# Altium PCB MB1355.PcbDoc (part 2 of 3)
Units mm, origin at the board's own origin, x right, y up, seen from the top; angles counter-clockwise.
Board outline 70.13 x 64.58 mm, 4 copper layers (L1, L2, L3, L4), stack 1.565 mm thick; 206 components, 160 nets, 707 pads, 1364 vias.
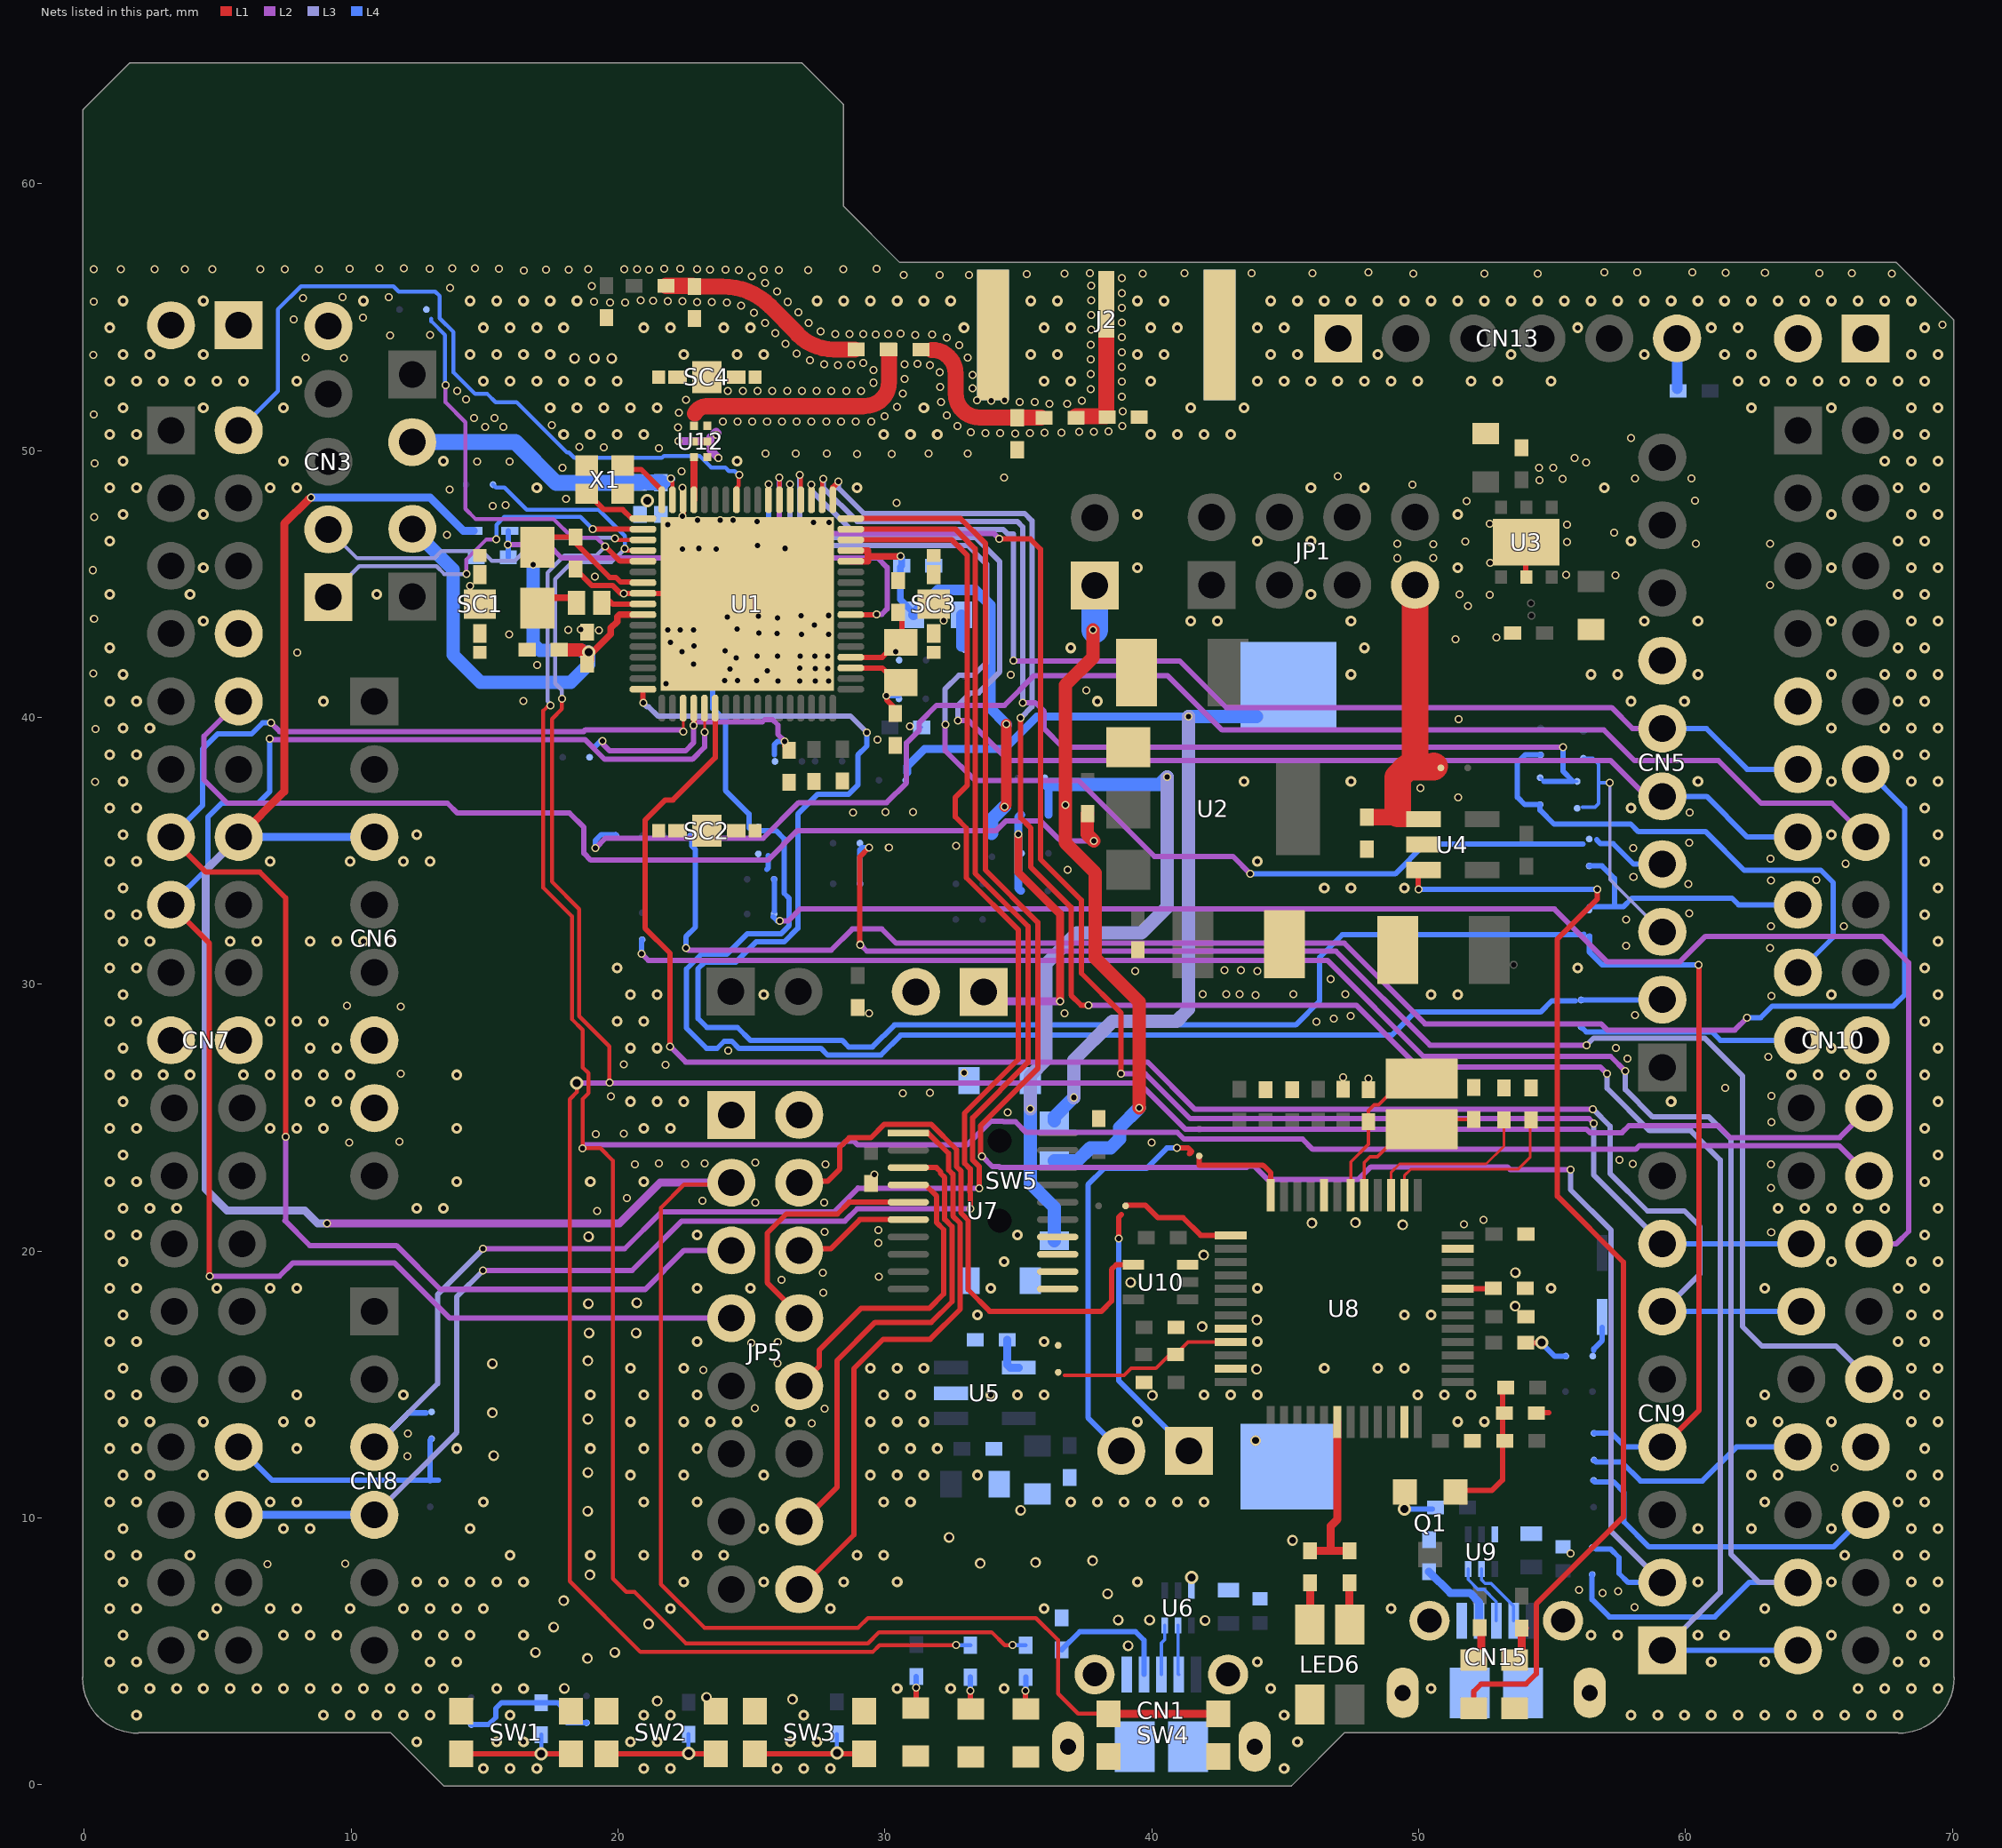
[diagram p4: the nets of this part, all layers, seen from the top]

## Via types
v1: diameter 0.3, hole 0.2, L1 to L4, tented both sides, 662 vias
v2: diameter 0.403, hole 0.2, L1 to L4, tented both sides, 628 vias
v3: diameter 0.4, hole 0.25, L1 to L4, tented both sides, 50 vias
v4: diameter 0.5, hole 0.3, L1 to L4, tented both sides, 24 vias

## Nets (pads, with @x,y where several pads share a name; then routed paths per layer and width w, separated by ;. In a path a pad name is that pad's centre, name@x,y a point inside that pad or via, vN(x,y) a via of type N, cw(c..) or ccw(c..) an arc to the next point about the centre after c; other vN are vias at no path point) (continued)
GND: C1.1 C2.2 C3.1 C6.2 C7.2 C8.2 C9.2 C10.2 C11.2 C12.2 C13.2 C14.2 C15.2 C16.2 C17.2 C18.2 C19.2 C20.2 C21.2 C22.2 C23.2 C24.2 C25.2 C26.2 C27.2 C28.2 C29.2 C31.2 C32.2 C33.1 C34.1 C36.2 C37.1 C39.1 C40.1 C41.2 C42.1 C43.2 C44.1 C45.1 C46.1 C47.2 C48.2 C49.2 C50.2 CN1.5 CN1.6 CN3.5 CN4.2 CN5.7 CN6.6 CN6.7 CN7.8 CN7.19 CN7.20 CN10.9 CN10.20 CN10.32 CN11.1 CN11.2 CN12.1 CN12.2 CN13.1 CN15.5 CN15.6 J2.2 JP5.1 JP5.2 LED1.K LED2.K LED3.K LED5.K LED6.1 R1.1 R6.2 R15.2 R18.2 R19.1 R20.1 R22.2 R23.1 R28.2 SB40.2 SC1.1 SC2.1 SC3.1 SC4.1 SK_BT1.2 SW1.1 SW2.1 SW3.1 SW4.2 SW5.0 U1.32 U1.42 U1.69 U2.1 U3.2 U3.7 U4.2 U5.2 U6.3 U7.11 U7.12 U7.13 U7.14 U8.8 U8.20 U8.23 U8.35 U8.47 U9.3 U10.3 U11.2 U12.A2 U12.B1 U12.B2 U12.B3 U13.2 X1.2 X1.4 | length 16
  L1 w0.2: C29.2@18.408,45.56 19.016,44.952 19.795,44.952 20.095,44.652 v1(20.217,44.652) U1.42@20.941,44.652 U1.69@24.444,44.652 ; U1.32@22.444,48.155 22.444,46.652 U1.69@24.444,44.652 ; U1.69@24.844,44.252 U1.69@24.444,44.652 ; U10.3@41.346,19.486 U10.3@41.543,19.486 ; U3.2@54.006,45.249 U3.7@54.006,46.549 ; R20.1@54.415,13.933 54.432,13.95 54.877,13.95
  L2 w0.3: v1(22.265,50.348) 23.464,50.348 ; v1(23.704,50.581) 23.704,50.623 23.733,50.653 23.674,50.712 23.464,50.502 23.464,50.348 ; v1(23.771,49.717) 23.464,50.024 23.464,50.348
  L4 w0.1: R6.2@31.304,39.705 R6.2@31.38,39.629
  other v1: 58.089,6.659 56.89,7.185 57.479,7.248 56.006,7.312 6.874,8.268 9.773,8.28 55.692,8.664 65.578,11.882 12.106,12.308 12.128,13.159 27.267,13.543 25.131,14.115 27.738,14.101 23.191,15.548 25.975,15.801 24.989,16.555 25.986,16.588 27.699,18.442 26.12,18.92 29.772,19.049 27.683,19.187 29.764,20.312 63.209,20.704 27.746,20.728 29.756,20.782 51.697,21.007 52.429,21.175 19.224,21.5 25.151,21.82 27.73,21.827 23.17,21.88 20.338,21.985 63.198,22.366 29.607,22.864 20.627,23.256 27.767,23.255 63.198,23.251 21.531,23.283 22.514,23.27 23.249,23.283 58.02,23.278 25.142,23.313 57.529,23.417 9.928,24.068 39.992,24.069 11.816,24.106 19.176,24.379 20.219,24.406 63.219,24.838 34.599,25.195 19.734,25.806 63.213,25.81 30.669,25.913 31.694,25.926 61.481,26.123 48.119,26.473 47.162,26.517 11.864,26.655 32.965,26.688 21.787,26.99 20.211,27.005 57.829,27.221 63.099,27.287 24.124,27.513 57.383,27.621 46.167,28.602 46.821,28.721 47.455,28.806 58.1,28.839 29.408,28.92 36.729,28.91 11.853,29.17 9.839,29.191 63.219,29.561 43.897,29.598 41.914,29.622 42.787,29.635 43.298,29.622 45.306,29.635 47.251,29.622 46.703,30.196 39.377,30.489 43.959,30.495 42.725,30.52 43.336,30.533 63.162,31.354 57.771,31.446 65.925,32.172 63.205,32.179 57.771,32.43 60.145,32.663 60.106,33.751 63.205,33.886 64.906,33.903 58.048,34.017 36.849,34.283 65.999,34.515 63.19,34.711 58.035,35.105 30.148,35.125 32.675,35.196 60.145,35.304 28.808,36.439 60.159,36.432 30.015,36.451 31.047,36.457 51.486,36.998 50.072,37.361 0.404,37.581 29.719,39.171 0.422,39.565 30.941,39.672 51.491,39.926 16.455,40.614 37.541,41.021 21.805,41.262 25.989,41.37 26.809,41.363 27.396,41.369 27.884,41.368 23.996,41.375 24.487,41.378 25.194,41.375 34.716,41.6 0.347,41.643 25.601,41.752 24.202,41.814 27.851,41.825 26.813,41.841 27.389,41.837 16.966,41.971 22.825,42.002 24.434,42.224 25.208,42.295 25.974,42.29 26.822,42.297 27.38,42.297 27.866,42.294 7.988,42.427 22.403,42.465 24.017,42.505 22.847,42.684 21.972,42.82 51.378,42.924 52.916,42.989 15.928,43.112 26.871,43.112 27.884,43.112 25.271,43.16 25.966,43.151 19.287,43.27 21.859,43.276 18.144,43.285 18.601,43.291 22.336,43.282 22.832,43.285 24.461,43.32 27.352,43.46 32.199,43.624 0.366,43.702 25.984,43.721 24.095,43.765 25.253,43.801 26.866,43.807 27.884,43.821 51.843,44.182 52.658,44.589 51.534,44.616 14.455,44.924 63.174,44.969 19.127,45.27 57.366,45.333 55.525,45.35 0.329,45.519 52.676,45.793 49.205,45.968 50.548,45.982 22.413,46.302 23.677,46.302 23.023,46.334 26.261,46.334 25.223,46.447 50.552,46.492 49.205,46.502 60.394,46.51 63.161,46.514 55.552,46.572 51.755,46.598 13.594,46.838 57.331,46.926 21.859,47.223 55.561,47.218 52.667,47.253 27.325,47.312 27.903,47.312 25.211,47.337 22.976,47.389 24.312,47.387 23.828,47.396 0.366,47.503 22.419,47.539 15.305,47.917 15.791,47.96 30.433,48.039 51.799,48.112 60.359,48.116 18.049,48.184 13.685,48.547 22.422,48.601 49.759,48.728 54.525,48.882 55.393,48.944 58.11,48.961 60.216,48.952 34.468,48.992 46.973,49.04 22.387,49.224 17.92,49.351 54.516,49.36 55.047,49.36 0.393,49.523 56.278,49.563 14.725,49.596 15.936,49.582 55.835,49.723 28.953,49.869 30.261,49.869 25.529,49.882 26.662,49.894 27.833,49.894 31.631,49.894 33.101,49.881 21.54,50.083 18.551,50.133 19.463,50.128 57.959,50.466 34.876,50.636 33.768,50.654 34.322,50.654 35.429,50.654 33.215,50.692 35.983,50.677 36.611,50.677 37.276,50.697 37.829,50.708 38.383,50.724 15.015,50.882 15.71,50.889 22.247,50.875 38.901,50.92 32.711,50.923 17.525,50.951 23.924,51.081 24.478,51.081 25.032,51.081 25.586,51.081 26.14,51.081 26.694,51.081 27.248,51.081 27.802,51.081 28.356,51.081 28.91,51.081 29.482,51.094 14.603,51.217 15.376,51.217 29.99,51.281 32.323,51.317 0.351,51.352 22.28,51.417 38.918,51.474 30.455,51.638 36.159,51.755 36.835,51.758 32.107,51.828 35.054,51.822 35.608,51.816 33.977,51.87 34.485,51.882 37.378,51.87 22.543,51.905 33.448,51.888 14.314,51.912 38.877,52.026 30.673,52.131 13.973,52.242 24.12,52.243 24.674,52.243 25.228,52.243 25.782,52.243 26.336,52.243 26.89,52.243 27.444,52.243 27.998,52.243 28.552,52.243 29.106,52.243 37.715,52.31 33.28,52.331 32.073,52.38 29.571,52.544 38.877,52.58 30.739,52.681 33.28,52.838 37.715,52.864 32.06,52.934 29.57,53.012 38.877,53.134 31.688,53.198 28.242,53.209 28.741,53.215 27.725,53.24 30.739,53.235 31.214,53.247 29.195,53.277 27.188,53.378 37.715,53.418 8.295,53.481 9.731,53.469 33.097,53.489 0.34,53.581 26.697,53.634 38.877,53.688 32.782,53.944 26.277,53.995 37.715,53.972 32.313,54.24 38.877,54.242 11.468,54.311 12.962,54.333 29.654,54.35 31.131,54.338 28.142,54.372 28.681,54.374 29.183,54.371 30.126,54.367 31.772,54.357 25.895,54.396 30.59,54.376 27.597,54.47 37.723,54.526 69.63,54.721 25.504,54.789 27.143,54.788 38.873,54.796 7.855,54.909 10.443,54.978 37.723,55.08 25.097,55.164 26.753,55.181 38.873,55.35 24.615,55.438 19.709,55.555 20.264,55.555 22.966,55.557 24.074,55.557 0.361,55.589 19.107,55.579 21.859,55.592 22.413,55.592 23.52,55.57 26.362,55.574 21.318,55.618 20.843,55.626 37.723,55.634 8.19,55.716 9.682,55.746 11.417,55.754 38.873,55.904 25.962,55.957 13.704,56.094 19.012,56.157 37.723,56.188 25.514,56.283 38.873,56.458 25.016,56.526 30.708,56.586 32.046,56.586 33.153,56.586 35.321,56.609 36.728,56.632 39.657,56.632 49.805,56.632 52.458,56.632 54.464,56.632 67.729,56.636 37.686,56.641 41.225,56.655 43.739,56.655 46.023,56.655 65.009,56.649 66.224,56.649 48.122,56.678 56.956,56.676 58.196,56.675 60.256,56.675 61.51,56.662 62.976,56.662 16.466,56.752 17.301,56.773 18.146,56.783 21.168,56.783 23.448,56.786 24.032,56.786 24.531,56.771 25.468,56.786 26.026,56.77 27.134,56.77 0.361,56.805 1.375,56.805 2.644,56.794 3.774,56.805 4.81,56.805 6.607,56.805 7.515,56.805 8.805,56.805 18.886,56.794 20.231,56.791 20.712,56.797 21.729,56.807 22.331,56.807 22.957,56.795 28.448,56.793 9.946,56.815 11.055,56.836 11.975,56.826 12.936,56.815 13.792,56.826 14.648,56.826 15.547,56.815 29.694,56.816
  other v2: 14.962,0.607 15.962,0.607 16.962,0.607 20.962,0.607 21.962,0.607 25.962,0.607 26.962,0.607 27.962,0.607 44.962,0.607 12.462,1.607 15.462,1.607 16.462,1.607 20.462,1.607 21.462,1.607 26.462,1.607 27.462,1.607 45.462,1.607 1.962,2.607 8.962,2.607 9.962,2.607 10.962,2.607 11.962,2.607 12.962,2.607 15.962,2.607 20.962,2.607 21.962,2.607 26.962,2.607 44.962,2.607 57.962,2.607 58.962,2.607 59.962,2.607 60.962,2.607 61.962,2.607 62.962,2.607 63.962,2.607 64.962,2.607 65.962,2.607 66.962,2.607 67.962,2.607 1.462,3.607 2.462,3.607 3.462,3.607 4.462,3.607 5.462,3.607 6.462,3.607 7.462,3.607 8.462,3.607 9.462,3.607 10.462,3.607 11.462,3.607 12.462,3.607 13.462,3.607 15.462,3.607 16.462,3.607 30.462,3.607 32.462,3.607 34.462,3.607 44.462,3.607 50.462,3.607 66.462,3.607 67.462,3.607 68.462,3.607 69.462,3.607 0.962,4.607 1.962,4.607 12.962,4.607 13.962,4.607 43.962,4.607 60.962,4.607 62.962,4.607 67.962,4.607 68.962,4.607 1.462,5.607 4.462,5.607 7.462,5.607 8.462,5.607 9.462,5.607 12.462,5.607 13.462,5.607 14.462,5.607 16.462,5.607 56.462,5.607 57.462,5.607 60.462,5.607 61.462,5.607 65.462,5.607 68.462,5.607 69.462,5.607 0.962,6.607 1.962,6.607 4.962,6.607 6.962,6.607 7.962,6.607 9.962,6.607 11.962,6.607 12.962,6.607 13.962,6.607 14.962,6.607 21.962,6.607 27.962,6.607 35.962,6.607 48.962,6.607 62.962,6.607 67.962,6.607 68.962,6.607 1.462,7.607 12.462,7.607 13.462,7.607 14.462,7.607 15.462,7.607 16.462,7.607 22.462,7.607 25.462,7.607 28.462,7.607 30.462,7.607 39.462,7.607 60.462,7.607 65.462,7.607 68.462,7.607 69.462,7.607 0.962,8.607 1.962,8.607 3.962,8.607 15.962,8.607 18.962,8.607 20.962,8.607 22.962,8.607 23.962,8.607 28.962,8.607 29.962,8.607 65.962,8.607 67.962,8.607 68.962,8.607 1.462,9.607 7.462,9.607 8.462,9.607 14.462,9.607 25.462,9.607 60.462,9.607 62.462,9.607 65.462,9.607 68.462,9.607 69.462,9.607 0.962,10.607 1.962,10.607 6.962,10.607 7.962,10.607 14.962,10.607 20.962,10.607 22.962,10.607 29.962,10.607 30.962,10.607 36.962,10.607 37.962,10.607 38.962,10.607 39.962,10.607 40.962,10.607 41.962,10.607 62.962,10.607 67.962,10.607 68.962,10.607 1.462,11.607 2.462,11.607 4.462,11.607 20.462,11.607 22.462,11.607 25.462,11.607 29.462,11.607 30.462,11.607 31.462,11.607 33.462,11.607 62.462,11.607 63.462,11.607 68.462,11.607 69.462,11.607 0.962,12.607 1.962,12.607 7.962,12.607 13.962,12.607 18.962,12.607 20.962,12.607 22.962,12.607 29.962,12.607 30.962,12.607 31.962,12.607 68.962,12.607 1.462,13.607 2.462,13.607 4.462,13.607 7.462,13.607 8.462,13.607 20.462,13.607 22.462,13.607 23.462,13.607 24.462,13.607 26.462,13.607 29.462,13.607 30.462,13.607 31.462,13.607 39.462,13.607 51.462,13.607 52.462,13.607 62.462,13.607 63.462,13.607 65.462,13.607 68.462,13.607 69.462,13.607 0.962,14.607 1.962,14.607 7.962,14.607 11.962,14.607 18.962,14.607 20.962,14.607 22.962,14.607 29.962,14.607 30.962,14.607 33.962,14.607 34.962,14.607 35.962,14.607 41.962,14.607 42.962,14.607 43.962,14.607 49.962,14.607 50.962,14.607 51.962,14.607 62.962,14.607 67.962,14.607 68.962,14.607 1.462,15.607 20.462,15.607 22.462,15.607 29.462,15.607 30.462,15.607 31.462,15.607 46.462,15.607 48.462,15.607 49.462,15.607 68.462,15.607 69.462,15.607 0.962,16.607 1.962,16.607 22.962,16.607 35.962,16.607 43.962,16.607 67.962,16.607 68.962,16.607 1.462,17.607 33.462,17.607 49.462,17.607 50.462,17.607 68.462,17.607 69.462,17.607 0.962,18.607 1.962,18.607 4.962,18.607 6.962,18.607 7.962,18.607 22.962,18.607 24.962,18.607 33.962,18.607 43.962,18.607 54.962,18.607 62.962,18.607 67.962,18.607 68.962,18.607 1.462,19.607 34.462,19.607 65.462,19.607 68.462,19.607 69.462,19.607 0.962,20.607 1.962,20.607 22.962,20.607 34.962,20.607 68.962,20.607 1.462,21.607 2.462,21.607 3.462,21.607 12.462,21.607 13.462,21.607 63.462,21.607 64.462,21.607 65.462,21.607 66.462,21.607 67.462,21.607 69.462,21.607 0.962,22.607 1.962,22.607 13.962,22.607 18.962,22.607 20.962,22.607 68.962,22.607 1.462,23.607 69.462,23.607 0.962,24.607 1.962,24.607 6.962,24.607 7.962,24.607 8.962,24.607 13.962,24.607 20.962,24.607 21.962,24.607 68.962,24.607 1.462,25.607 8.462,25.607 9.462,25.607 20.462,25.607 21.462,25.607 22.462,25.607 59.462,25.607 69.462,25.607 0.962,26.607 1.962,26.607 2.962,26.607 3.962,26.607 5.962,26.607 6.962,26.607 7.962,26.607 8.962,26.607 9.962,26.607 13.962,26.607 63.962,26.607 64.962,26.607 65.962,26.607 66.962,26.607 68.962,26.607 1.462,27.607 8.462,27.607 9.462,27.607 20.462,27.607 21.462,27.607 65.462,27.607 69.462,27.607 0.962,28.607 1.962,28.607 6.962,28.607 7.962,28.607 8.962,28.607 19.962,28.607 20.962,28.607 68.962,28.607 1.462,29.607 20.462,29.607 21.462,29.607 25.462,29.607 50.462,29.607 51.462,29.607 65.462,29.607 69.462,29.607 0.962,30.607 1.962,30.607 19.962,30.607 55.962,30.607 68.962,30.607 1.462,31.607 2.462,31.607 5.462,31.607 6.462,31.607 8.462,31.607 9.462,31.607 10.462,31.607 11.462,31.607 69.462,31.607 0.962,32.607 1.962,32.607 68.962,32.607 1.462,33.607 46.462,33.607 47.462,33.607 49.462,33.607 69.462,33.607 0.962,34.607 1.962,34.607 6.962,34.607 9.962,34.607 11.962,34.607 12.962,34.607 43.962,34.607 68.962,34.607 1.462,35.607 12.462,35.607 65.462,35.607 69.462,35.607 0.962,36.607 1.962,36.607 57.962,36.607 68.962,36.607 1.462,37.607 43.462,37.607 47.462,37.607 60.462,37.607 65.462,37.607 68.462,37.607 69.462,37.607 0.962,38.607 1.962,38.607 67.962,38.607 68.962,38.607 1.462,39.607 2.462,39.607 65.462,39.607 67.462,39.607 68.462,39.607 69.462,39.607 0.962,40.607 1.962,40.607 8.962,40.607 37.962,40.607 57.962,40.607 59.962,40.607 67.962,40.607 68.962,40.607 1.462,41.607 47.462,41.607 56.462,41.607 57.462,41.607 60.462,41.607 65.462,41.607 67.462,41.607 68.462,41.607 69.462,41.607 0.962,42.607 36.962,42.607 47.962,42.607 67.962,42.607 68.962,42.607 4.462,43.607 41.462,43.607 42.462,43.607 47.462,43.607 58.462,43.607 60.462,43.607 65.462,43.607 68.462,43.607 69.462,43.607 0.962,44.607 3.962,44.607 10.962,44.607 45.962,44.607 67.962,44.607 68.962,44.607 4.462,45.607 39.462,45.607 51.462,45.607 65.462,45.607 68.462,45.607 69.462,45.607 0.962,46.607 43.962,46.607 45.962,46.607 57.962,46.607 67.962,46.607 68.962,46.607 1.462,47.607 4.462,47.607 39.462,47.607 51.462,47.607 65.462,47.607 68.462,47.607 69.462,47.607 0.962,48.607 1.962,48.607 6.962,48.607 7.962,48.607 16.962,48.607 28.962,48.607 45.962,48.607 47.962,48.607 56.962,48.607 67.962,48.607 68.962,48.607 1.462,49.607 7.462,49.607 13.462,49.607 24.462,49.607 67.462,49.607 68.462,49.607 69.462,49.607 0.962,50.607 1.962,50.607 17.962,50.607 18.962,50.607 19.962,50.607 20.962,50.607 29.962,50.607 30.962,50.607 31.962,50.607 39.962,50.607 40.962,50.607 41.962,50.607 42.962,50.607 67.962,50.607 68.962,50.607 1.462,51.607 4.462,51.607 7.462,51.607 17.462,51.607 18.462,51.607 19.462,51.607 20.462,51.607 21.462,51.607 31.462,51.607 41.462,51.607 43.462,51.607 62.462,51.607 65.462,51.607 68.462,51.607 69.462,51.607 0.962,52.607 1.962,52.607 2.962,52.607 3.962,52.607 4.962,52.607 5.962,52.607 7.962,52.607 14.962,52.607 15.962,52.607 16.962,52.607 17.962,52.607 18.962,52.607 19.962,52.607 35.962,52.607 36.962,52.607 39.962,52.607 43.962,52.607 44.962,52.607 45.962,52.607 46.962,52.607 47.962,52.607 48.962,52.607 49.962,52.607 51.962,52.607 52.962,52.607 54.962,52.607 61.962,52.607 62.962,52.607 63.962,52.607 64.962,52.607 65.962,52.607 66.962,52.607 67.962,52.607 68.962,52.607 1.462,53.607 2.462,53.607 4.462,53.607 14.462,53.607 15.462,53.607 16.462,53.607 17.462,53.607 22.462,53.607 24.462,53.607 25.462,53.607 35.462,53.607 36.462,53.607 39.462,53.607 40.462,53.607 44.462,53.607 45.462,53.607 48.462,53.607 53.462,53.607 58.462,53.607 61.462,53.607 62.462,53.607 68.462,53.607 69.462,53.607 0.962,54.607 14.962,54.607 15.962,54.607 16.962,54.607 17.962,54.607 20.962,54.607 21.962,54.607 23.962,54.607 24.962,54.607 32.962,54.607 35.962,54.607 36.962,54.607 39.962,54.607 40.962,54.607 43.962,54.607 44.962,54.607 55.962,54.607 60.962,54.607 61.962,54.607 68.962,54.607 1.462,55.607 4.462,55.607 10.462,55.607 14.462,55.607 15.462,55.607 16.462,55.607 17.462,55.607 18.462,55.607 27.462,55.607 28.462,55.607 29.462,55.607 30.462,55.607 31.462,55.607 32.462,55.607 35.462,55.607 36.462,55.607 39.462,55.607 40.462,55.607 44.462,55.607 45.462,55.607 46.462,55.607 47.462,55.607 48.462,55.607 49.462,55.607 50.462,55.607 51.462,55.607 52.462,55.607 53.462,55.607 54.462,55.607 55.462,55.607 56.462,55.607 57.462,55.607 58.462,55.607 59.462,55.607 60.462,55.607 61.462,55.607 62.462,55.607 63.462,55.607 64.462,55.607 65.462,55.607 66.462,55.607 67.462,55.607 68.462,55.607
  other v3: 21.468,3.14 26.541,3.202 23.321,3.279 17.987,3.611 18.859,4.734 16.908,4.964 19.881,4.959 39.114,5.213 17.589,5.907 21.142,6.031 41.994,6.163 38.741,6.178 39.919,6.178 17.966,6.903 38.346,7.158 18.951,7.867 33.575,8.297 35.647,8.336 37.784,8.4 45.278,9.161 32.403,9.275 18.866,10.252 35.086,10.291 18.874,11.701 15.342,12.333 43.89,12.9 18.874,13.706 15.297,13.944 40.021,14.59 43.928,15.579 15.297,15.779 18.874,15.89 18.917,16.933 20.677,16.933 41.889,17.175 43.938,17.422 53.618,17.942 18.892,18.029 20.703,18.063 39.205,18.833 53.625,19.193 41.945,19.849 18.9,20.548 49.4,20.983 46.002,21.051 47.634,21.07 18.37,53.457 19.116,53.457 19.762,53.457
  other v4: 41.485,7.776 21.099,48.131
LED_STLK: R25.2 R27.2 U8.30 | length 6.4
  L1 w0.3: R25.2@45.93,8.773 46.71,8.773 ; U8.30@46.96,13.596 46.96,9.952 46.71,9.702 46.71,8.773 ; R27.2@47.41,8.773 46.71,8.773
NetC3_2: C3.2 D1.A U1.8 | length 18.6
  L1 w0.2: U1.8@28.723,43.851 U1.8@28.722,43.852 29.677,43.852 v1(29.695,43.87)
  L2 w0.2: v1(15.88,46.479) 17.382,46.479 17.886,45.975 20.106,45.975 20.112,45.969 20.402,45.969 20.408,45.975 22.246,45.975 22.268,45.952 22.558,45.952 22.58,45.975 23.509,45.975 23.532,45.952 23.822,45.952 23.844,45.975 24.275,45.975 29.732,45.975 30.087,45.62 30.087,44.069 29.888,43.87 v1(29.695,43.87)
  L4 w0.2: C3.2@15.881,45.998 D1.A@15.881,46.998
NetC6_1: C6.1 SB45.1 U1.3 X2.1 | length 3.1
  L1 w0.2: U1.3@28.722,41.852 29.899,41.852 X2.1@30.444,41.307 ; v1(30.058,40.815) 30.07,40.803 30.07,40.654 C6.1@30.393,40.331
  L4 w0.2: v1(30.058,40.815) 30.529,40.815 30.545,40.831
NetC7_1: C7.1 SB46.1 U1.4 X2.2 | length 3
  L1 w0.2: U1.4@28.722,42.252 29.899,42.252 30.454,42.807 X2.2@30.591,42.807 30.643,42.859 C7.1@30.643,43.695
  other v1: 30.403,42.461
NetC12_1: C12.1 JP1.7 SB25.1 U4.1 | length 11.7
  L1 w0.6: C12.1@48.268,36.263 49.131,36.263 49.212,36.182 U4.1@50.175,36.182
  L1 w1: 49.215,36.394 49.215,37.76 49.595,38.14 49.865,38.14 ; JP1.7@49.865,44.965 49.865,38.14 ; 50.569,38.192 50.595,38.166 50.569,38.14 49.865,38.14
NetC23_1: C23.1 C24.1 JP6.2 SB31.2 U1.44 | length 15.4
  L1 w0.25: C24.1@18.999,42.147 18.999,42.386 19.732,43.119 19.732,43.347 19.975,43.59 19.975,43.773 20.054,43.852 U1.44@20.941,43.852
  L1 w0.5: C23.1@18.076,42.528 18.618,42.528
  L4 w0.5: JP6.2@12.296,47.063 13.824,45.535 13.824,42.342 14.844,41.322 18.232,41.322 18.895,41.984 v4(18.895,42.446) 18.697,42.446 18.637,42.506
NetC26_1: C26.1 U5.4 | length 1.4
  L4 w0.3: C26.1@34.589,16.674 34.589,15.743 34.695,15.636 U5.4@35.02,15.636
NetC29_1: C29.1 L1.1 SB31.1 U1.41 | length 8.7
  L1 w0.2: L1.1@16.98,46.377 17.36,46.758 C29.1@18.408,46.758 18.408,46.529 19.685,45.252 19.919,45.252 20.101,45.07 20.941,45.07 U1.41@20.941,45.052
  L4 w0.5: v1(16.817,45.726) 16.817,42.763 17.074,42.506 SB31.1@17.502,42.506
NetC31_1: C31.1 SB33.1 SB34.1 U1.55 | length 10.7
  L1 w0.2: v1(22.836,39.702) 22.835,39.702 22.844,39.711 U1.55@22.844,40.349 ; v1(26.249,39.108) 26.249,38.922 C31.1@26.409,38.762
  L2 w0.2: v1(19.411,39.111) 19.411,39.029 19.692,38.748 22.531,38.748 22.836,39.053 v1(22.836,39.702) 22.836,39.718 22.951,39.833 25.412,39.833 25.5,39.921 25.79,39.921 25.995,39.716 25.995,39.362 v1(26.249,39.108)
  L4 w0.2: 19.122,38.894 19.339,39.111 v1(19.411,39.111) ; 25.863,38.605 25.863,38.991 25.98,39.108 v1(26.249,39.108)
NetC32_1: C32.1 L2.2 SB49.1 U1.13 U1.14 | length 17.8
  L1 w0.25: U1.13@28.722,45.852 29.365,45.852 29.365,46.252 U1.14@28.722,46.252 ; 29.491,46.042 30.588,46.042 v1(30.592,46.046)
  L1 w0.4: v1(34.485,36.659) 34.551,36.725 v1(34.551,39.746)
  L4 w0.25: v1(30.592,46.046) 30.631,46.007 C32.1@30.631,45.689 30.576,45.634 30.576,44.416 31.063,43.929 L2.2@31.063,43.852
  L4 w0.4: L2.2@31.063,43.852 31.985,44.774 33.387,44.774 33.943,44.218 33.943,40.354 v1(34.551,39.746) v1@34.559,39.738
  L4 w0.5: 33.994,35.649 33.994,36.168 v1(34.485,36.659)
NetC33_2: C33.2 C34.2 JP4.2 U1.33 | length 10.7
  L1 w0.15: U1.33@22.044,48.155 v1@22.044,48.884
  L4 w0.3: C34.2@21.752,48.698 v1@21.991,48.937
  L4 w0.6: JP4.2@12.289,50.316 16.154,50.316 17.679,48.791 20.371,48.791 20.384,48.804 C33.2@20.828,48.804 ; 21.155,48.799 C34.2@21.611,48.799
  other v1: 21.988,48.952
NetC36_1: C36.1 L3.1 R5.2 | length 7.9
  L1 w0.32: C36.1@22.798,56.173 C36.1@22.82,56.151 ; 26.728,54.383 26.728,54.387
  L1 w0.6: L3.1@21.8,56.173 C36.1@22.798,56.173 ; C36.1@22.82,56.151 23.912,56.151 cw(c23.912,53.611) 25.708,55.407 26.728,54.383 ; 26.728,54.358 ccw(c28.097,55.726) 28.097,53.791 R5.2@28.881,53.791
NetC39_2: C39.2 L4.1 R13.2 | length 5.8
  L1 w0.6: 31.754,53.775 cw(c31.754,52.875) 32.654,52.875 32.654,52.179 ; 32.655,52.135 ccw(c33.555,52.135) 33.555,51.235 L4.1@35.841,51.235
NetC40_2: C40.2 J2.1 L4.2 | length 5.3
  L1 w0.32: C40.2@38.275,51.289 C40.2@38.296,51.31 ; J2.1@38.298,54.253 J2.1@38.298,55.481
  L1 w0.6: L4.2@37.169,51.289 C40.2@38.275,51.289 ; C40.2@38.296,51.31 38.296,54.251 J2.1@38.298,54.253
NetC44_2: C44.2 U8.6 X3.2 | length 5.3
  L1 w0.127: U8.6@47.46,22.096 47.46,23.346 48.12,24.006 C44.2@48.12,24.857 48.12,25.269 48.337,25.486 48.496,25.486 49.138,26.128 X3.2@49.138,26.65
NetC45_2: C45.2 U8.5 X3.1 | length 5.8
  L1 w0.127: U8.5@47.96,22.096 47.96,23.316 48.178,23.534 48.446,23.534 49.362,24.45 X3.1@50.738,24.45 ; X3.1@50.942,24.44 51.435,24.933 C45.2@52.064,24.933
NetCN1_2: CN1.2 U6.5 | length 1.9
  L4 w0.12: U6.5@40.986,5.98 40.978,5.973 40.978,4.167 CN1.2@41.009,4.135
NetCN1_3: CN1.3 U6.6 | length 1.9
  L4 w0.12: CN1.3@40.359,4.135 40.359,5.315 40.486,5.442 U6.6@40.486,5.98
NetCN1_4: CN1.4 R1.2 | length 4.8
  L4 w0.2: R1.2@36.627,5.061 37.299,5.733 39.394,5.733 39.709,5.418 CN1.4@39.709,4.135
NetCN3_1: CN3.1 U1.36 | length 14.2
  L1 w0.2: v1@19.044,47.052 19.058,47.065 20.927,47.065 U1.36@20.941,47.052
  L2 w0.15: v1(14.324,45.376) 14.324,45.925 15.072,46.674 v1(15.433,46.674)
  L3 w0.15: CN3.1@9.146,44.507 10.308,45.669 13.198,45.669 13.491,45.376 v1(14.324,45.376)
  L4 w0.15: v1(15.433,46.674) 15.433,46.644 15.445,46.632 15.445,47.22 15.738,47.514 18.595,47.514 v1(19.044,47.064)
NetCN3_2: CN3.2 U1.37 | length 13
  L1 w0.15: v1(19.886,46.715) 19.886,46.663 19.905,46.644 U1.37@20.933,46.644 ; U1.37@20.915,46.626 U1.37@20.933,46.644 ; U1.37@20.941,46.652 U1.37@20.933,46.644 ; U1.37@20.957,46.644 U1.37@20.933,46.644
  L3 w0.15: CN3.2@9.146,47.047 10.231,45.962 13.116,45.962 13.394,46.24 14.894,46.24 15.271,45.863 16.127,45.863 17.002,46.738 19.863,46.738 v1(19.886,46.715)
NetCN4_1: CN4.1 SB24.1 SB27.1 SB28.1 | length 12.8
  L1 w0.3: v1(35.008,35.615) 35.008,34.184 36.558,32.634 v1(36.558,29.366)
  L2 w0.3: CN4.1@33.71,29.707 34.051,29.366 v1(36.558,29.366)
  L4 w0.3: SB24.1@35.097,33.5 34.997,33.6 34.997,36.261 SB27.1@35.097,36.361
NetCN5_3: CN5.3 SB41.2 SB42.2 | length 9.6
  L3 w0.127: v1(57.165,37.557) 57.165,33.929 CN5.3@59.13,31.964
  L4 w0.127: 56.133,36.633 56.604,36.633 56.746,36.776 56.746,37.556 ; SB42.2@56.17,38.468 56.522,38.468 56.746,38.243 56.746,37.556 ; v1(57.165,37.557) 56.748,37.557 56.746,37.556
NetCN7_10: CN7.10 R33.1 | length 40.7
  L1 w0.5: R33.1@37.593,36.396 37.583,36.386 37.583,35.62 v1(37.828,35.375)
  L2 w0.2: CN7.10@5.79,40.6 4.487,39.297 4.487,37.662 5.363,36.787 13.609,36.787 13.977,36.419 18.188,36.419 18.722,35.885 18.722,34.911 18.98,34.653 25.619,34.653 26.723,35.757 34.172,35.757 34.54,36.125 35.827,36.125 36.504,35.448 36.522,35.448 36.595,35.375 v1(37.828,35.375)
NetCN7_32: CN7.32 SB14.1 SB16.1 | length 9.6
  L4 w0.2: CN7.32@5.79,12.66 7.038,11.412 13.278,11.412 ; SB16.1@12.962,11.426 12.962,12.915 SB14.1@13.016,12.969
NetCN10_12: CN10.12 SB2.2 | length 61.6
  L2 w0.2: v1(22.541,31.362) 22.626,31.277 27.986,31.277 28.778,32.069 29.891,32.069 30.416,31.543 47.213,31.543 50.24,28.516 56.839,28.516 57.068,28.287 61.848,28.287 v1(62.308,28.747)
  L4 w0.2: v1(22.541,31.362) 22.541,31.783 22.902,32.144 22.902,35.052 22.758,35.196 22.758,35.522 SB2.2@22.718,35.562 ; v1(62.308,28.747) 62.814,28.747 63.249,29.182 67.782,29.182 68.21,29.61 68.21,36.6 CN10.12@66.75,38.06
NetCN10_14: CN10.14 SB4.2 | length 55
  L2 w0.2: v1(19.158,35.099) 19.53,35.471 25.436,35.471 26.771,36.806 30.068,36.806 30.813,37.551 30.813,39.049 31.291,39.527 31.291,39.806 31.935,40.45 34.477,40.45 35.595,41.568 35.595,41.573 40.591,41.573 42.635,39.529 56.941,39.529 58.084,38.386 61.231,38.386 62.829,36.788 65.482,36.788 CN10.14@66.75,35.52
  L3 w0.2: v1@19.156,35.099 v1(19.158,35.099)
  L4 w0.2: v1(19.158,35.099) 19.158,35.396 19.366,35.604 SB4.2@19.919,35.604
NetCN10_15: CN10.15 SB1.1 SB3.1 | length 10.2
  L4 w0.2: SB1.1@56.39,34.434 56.869,34.434 57.334,33.969 57.334,32.904 ; SB3.1@56.4,32.904 57.334,32.904 ; CN10.15@64.21,32.98 61.984,32.98 61.74,33.224 57.99,33.224 57.67,32.904 57.334,32.904
NetCN10_17: CN10.17 SB5.1 SB6.1 | length 19.5
  L4 w0.2: SB6.1@54.57,38.594 53.988,38.594 53.702,38.308 53.702,37.012 53.98,36.734 SB5.1@54.55,36.734 54.55,36.524 55.07,36.004 57.945,36.004 58.235,35.714 60.759,35.714 62.199,34.274 65.07,34.274 65.53,33.814 65.53,31.76 CN10.17@64.21,30.44
NetCN10_19: CN10.19 SB8.1 | length 8.3
  L4 w0.2: SB8.1@56.09,28.404 56.28,28.214 60.99,28.214 61.304,27.9 CN10.19@64.21,27.9
NetCN10_26: CN10.26 SB7.2 SB9.2 SB10.2 | length 57.9
  L2 w0.2: v1(26.065,32.377) 26.379,32.377 26.821,32.819 55.09,32.819 57.069,30.84 59.784,30.84 60.745,31.801 67.363,31.801 68.36,30.804 68.36,20.738 67.902,20.28 CN10.26@66.877,20.28
  L4 w0.2: 25.573,34.302 25.626,34.355 25.626,34.821 ; SB7.2@25.811,32.528 25.962,32.377 v1(26.065,32.377) ; SB9.2@25.848,33.937 25.855,33.93 SB7.2@25.855,32.739
NetCN10_30: CN10.30 SB12.2 SB13.2 | length 55.7
  L1 w0.2: v1(29.081,31.485) 29.061,31.485 29.061,34.781 v1(29.404,35.124)
  L2 w0.2: v1(29.081,31.485) 29.323,31.243 46.895,31.243 50.419,27.719 v1(56.291,27.719)
  L3 w0.2: v1(56.291,27.719) 56.557,27.985 57.947,27.985 57.948,27.984 60.717,27.984 62.127,26.574 62.127,17.178 62.861,16.444 65.633,16.444 CN10.30@66.877,15.2
  L4 w0.2: SB12.2@29.052,33.784 29.052,35.035 29.141,35.124 v1(29.404,35.124)
NetCN10_31: CN10.31 SB11.1 | length 8.5
  L4 w0.2: SB11.1@56.571,12.169 56.641,12.099 57.599,12.099 58.31,11.388 60.634,11.388 61.906,12.66 CN10.31@64.21,12.66
NetCN10_34: CN10.34 SB17.2 | length 12.4
  L4 w0.2: SB17.2@56.54,11.406 56.595,11.351 57.312,11.351 57.698,10.965 57.698,9.852 58.635,8.915 65.545,8.915 CN10.34@66.75,10.12
NetCN10_35: CN10.35 SB15.1 SB18.1 | length 72.6
  L2 w0.2: v1(20.883,31.147) 21.132,30.898 46.579,30.898 50.179,27.298 57.192,27.298 v1(57.744,26.746)
  L3 w0.2: v1(57.744,26.746) 57.744,26.056 58.77,25.03 60.874,25.03 61.698,24.206 61.698,8.642 62.76,7.58 CN10.35@64.21,7.58
  L4 w0.2: v1(20.883,31.147) 20.883,31.649 SB18.1@20.905,31.671 ; SB15.1@56.498,7.881 56.498,6.942 57.144,6.296 61.096,6.296 62.38,7.58 CN10.35@64.21,7.58
NetCN13_6: CN13.6 R31.1 | length 1.9
  L4 w0.4: R31.1@59.68,52.325 CN13.6@59.68,54.204
NetCN14_1: CN14.1 SB39.2 U8.13 | length 14.4
  L1 w0.2: v1(38.769,20.473) 38.769,21.28 38.868,21.379 ; SB39.2@39.04,21.716 39.763,21.716 40.23,21.249 41.175,21.249 41.828,20.596 U8.13@42.96,20.596
  L4 w0.2: v1(38.769,20.473) 38.769,15.138 CN14.1@41.398,12.509
NetCN14_2: CN14.2 SB38.2 U8.12 | length 19.1
  L1 w0.2: v1(40.943,23.861) 41.364,23.861 41.496,23.729 41.416,23.649 ; 41.77,23.221 44.155,23.221 44.18,23.196 44.19,23.206 44.46,22.936 U8.12@44.46,22.096 ; 41.78,23.231 SB38.2@41.78,23.568
  L4 w0.2: CN14.2@38.858,12.509 37.61,13.757 37.61,22.492 38.214,23.096 39.803,23.096 40.568,23.861 v1(40.943,23.861)
NetCN15_2: CN15.2 U9.5 | length 2.6
  L4 w0.12: U9.5@52.352,8.086 52.352,7.685 52.491,7.546 52.715,7.546 53.557,6.703 CN15.2@53.557,6.15
NetCN15_3: CN15.3 U9.6 | length 2.5
  L4 w0.12: U9.6@51.852,8.086 51.852,7.695 52.225,7.322 52.451,7.322 52.907,6.866 CN15.3@52.907,6.15
NetCN15_4: CN15.4 R23.2 | length 3
  L4 w0.3: R23.2@50.39,7.985 51.186,7.189 51.915,7.189 52.257,6.847 CN15.4@52.257,6.15
NetD2_2: D2.2 SB36.1 | length 1
  L4 w0.2: 56.566,16.277 56.566,16.34 56.88,16.654 D2.2@56.88,17.144
NetJP2_1: JP2.1 SW5.2 | length 25.4
  L1 w0.5: v1(37.793,43.277) 37.793,42.245 36.759,41.211 v1(36.759,36.724) 36.759,35.305 37.887,34.177 37.887,30.978 39.524,29.341 v1(39.524,25.365)
  L4 w0.5: SW5.2@36.355,23.391 36.365,23.381 37.209,23.381 37.697,23.869 38.458,23.869 38.788,24.2 38.788,24.63 v1(39.524,25.365)
  L4 w1: v1@37.867,43.277 JP2.1@37.867,44.946
NetJP5_4: JP5.4 U10.4 | length 21
  L1 w0.2: JP5.4@26.859,22.627 27.861,22.627 28.316,23.082 28.316,23.901 28.663,24.247 29.472,24.247 29.98,24.756 31.733,24.756 32.687,23.802 32.687,23.166 32.845,23.008 32.845,21.439 33.119,21.165 33.119,18.557 33.925,17.751 38.116,17.751 38.492,18.127 38.492,19.314 38.664,19.486 U10.4@39.319,19.486
NetJP5_6: JP5.6 U7.6 | length 4.5
  L1 w0.2: JP5.6@26.859,20.087 27.971,20.087 29.065,21.181 U7.6@30.875,21.181
NetJP5_8: JP5.8 U7.5 | length 9.4
  L1 w0.2: JP5.8@26.859,17.547 25.589,18.817 25.589,20.672 26.306,21.389 28.223,21.389 28.665,21.831 U7.5@30.875,21.831
NetJP5_10: JP5.10 U7.4 | length 12.1
  L1 w0.2: JP5.10@26.859,15.007 27.549,15.697 27.549,16.3 29.104,17.856 31.665,17.856 32.204,18.395 32.204,20.807 31.945,21.067 31.945,22.059 31.522,22.481 U7.4@30.875,22.481
NetJP5_14: JP5.14 U7.3 | length 18.3
  L1 w0.2: JP5.14@26.783,9.726 28.2,11.143 28.2,15.893 29.635,17.329 31.738,17.329 32.519,18.11 32.519,20.917 32.245,21.191 32.245,22.76 32.087,22.917 32.087,22.974 31.93,23.131 U7.3@30.875,23.131
NetJP5_16: JP5.16 U7.1 | length 21.8
  L1 w0.2: JP5.16@26.859,7.387 28.841,9.369 28.841,15.603 29.938,16.7 31.698,16.7 32.819,17.821 32.819,21.041 32.545,21.315 32.545,22.884 32.387,23.042 32.387,23.662 31.618,24.431 U7.1@30.875,24.431
NetL1_2: L1.2 L5.1 | length 1.8
  L1 w0.25: L1.2@16.98,44.091 17.37,44.481 L5.1@18.614,44.481
NetL2_1: L2.1 SB35.1 | length 1.2
  L4 w0.4: 32.867,42.666 L2.1@32.867,43.852
NetL5_2: L5.2 U1.43 | length 1.5
  L1 w0.2: L5.2@19.564,44.481 19.793,44.252 U1.43@20.941,44.252
NetLED1_A: LED1.A R2.2 | length 1.2
  L1 w0.2: LED1.A@31.15,2.876 ccw(c31.1,2.926) 31.171,2.926 v1(31.171,3.645)
  L4 w0.2: v1(31.171,3.645) 31.171,4.06 R2.2@31.175,4.065
NetLED2_A: LED2.A R3.2 | length 1.2
  L1 w0.2: v1(33.198,3.52) 33.198,2.899 ccw(c33.273,2.899) LED2.A@33.22,2.846
  L4 w0.2: v1(33.198,3.52) 33.205,3.527 R3.2@33.205,4.035
NetLED3_A: LED3.A R4.2 | length 1.2
  L1 w0.2: v1(35.274,3.52) 35.274,2.852 LED3.A@35.28,2.846
  L4 w0.2: v1(35.274,3.52) v1(35.274,3.52) R4.2@35.275,4.035
NetLED4_A: LED4.A R12.2 | length 1.3
  L1 w0.3: LED4.A@52.069,4.672 52.34,4.943 R12.2@52.34,5.895
NetLED4_K: LED4.K U4.3 | length 43
  L1 w0.2: U4.3@49.983,34.265 49.983,33.573 v1(49.995,33.561) ; LED4.K@52.069,2.868 52.069,3.509 52.335,3.775 54.022,3.775 54.407,4.16 54.407,6.777 57.669,10.039 57.669,19.591 55.201,22.059 55.201,31.697 56.689,33.185 v1(56.689,33.561)
  L4 w0.2: v1(49.995,33.561) v1(56.689,33.561)
NetLED5_A: LED5.A R10.2 | length 1.4
  L1 w0.3: LED5.A@53.593,4.672 53.863,4.942 53.863,5.768 R10.2@53.97,5.875
NetLED6_2: LED6.2 R25.1 | length 1.6
  L1 w0.3: LED6.2@45.93,6.024 R25.1@45.93,7.575
NetLED6_3: LED6.3 R27.1 | length 1.6
  L1 w0.3: LED6.3@47.41,6.024 R27.1@47.41,7.575
NetQ1_1: Q1.1 R16.1 R17.1 R20.2 | length 5.4
  L1 w0.2: Q1.1@51.2,11.036 52.753,11.036 53.141,11.423 53.141,14.644 R17.1@53.114,14.67
NetQ1_2: Q1.2 R21.2 | length 1.8
  L1 w0.127: v4@49.477,10.329 49.491,10.343 Q1.2@49.491,11.079
  L4 w0.2: v4(49.46,10.334) R21.2@50.509,10.334
NetR5_1: R5.1 R13.1 U12.A1 | length 8.9
  L1 w0.6: 22.878,51.381 cw(c23.321,51.171) 23.321,51.662 ; 23.344,51.662 29.174,51.662 ; 29.258,51.669 ccw(c29.258,52.569) 30.158,52.569 R13.1@30.158,53.625
NetR7_1: R7.1 SW1.2 | length 4.8
  L1 w0.2: SW1.2@14.103,1.167 SW1.2@14.13,1.167 SW1.2@18.203,1.167
  L4 w0.15: v4(17.124,1.163) R7.1@17.124,1.879
NetR7_2: R7.2 SB47.1 SB48.1 | length 5.4
  L4 w0.2: SB47.1@14.505,2.259 15.154,2.259 15.422,2.527 15.422,2.867 15.632,3.077 R7.2@17.124,3.077 17.741,3.077 17.928,2.89 17.928,2.488 18.094,2.323 SB48.1@18.821,2.323
NetR8_1: R8.1 SW2.2 | length 4.8
  L1 w0.2: SW2.2@19.564,1.167 SW2.2@23.664,1.167
  L4 w0.15: R8.1@22.646,1.897 v4(22.646,1.172) v4@22.655,1.163
NetR9_1: R9.1 SW3.2 | length 4.8
  L1 w0.2: SW3.2@25.127,1.167 SW3.2@29.227,1.167
  L4 w0.15: R9.1@28.203,1.905 v4(28.203,1.19) v4@28.212,1.181
NetR14_1: R14.1 SB36.2 | length 1.7
  L1 w0.2: R14.1@54.009,16.566 54.588,16.566 v4@54.598,16.576
  L4 w0.2: v4@54.585,16.567 55.085,16.067 SB36.2@55.515,16.067
  other v4: 54.61,16.572
NetR18_1: R18.1 U8.2 | length 7.1
  L1 w0.1: U8.2@49.46,22.096 49.46,22.826 49.7,23.066 53.722,23.066 54.182,23.526 R18.1@54.182,24.857
NetR19_2: R19.2 U8.44 | length 1.3
  L1 w0.2: U8.44@51.46,18.596 R19.2@52.791,18.596
NetR22_1: R22.1 U8.3 | length 6.5
  L1 w0.1: U8.3@48.96,22.096 48.96,22.946 49.28,23.266 52.531,23.266 53.194,23.929 R22.1@53.194,24.923
NetR30_2: R30.2 SB40.1 U8.21 | length 6.8
  L1 w0.127: 36.72,15.346 38.967,15.346 39.231,15.609 40.155,15.609 40.672,16.126 R30.2@40.889,16.126 41.359,16.596 U8.21@42.96,16.596
NetSB26_1: SB26.1 SB27.2 SW5.1 | length 27.2
  L3 w0.5: v1(35.455,25.337) 35.455,26.587 36.027,27.158 36.027,30.754 37.2,31.927 39.615,31.927 40.579,32.891 v1(40.579,37.767)
  L4 w0.3: SB27.2@36.13,36.348 36.13,37.346 35.994,37.482 36.227,37.482
  L4 w0.5: v1(35.455,25.337) 35.455,24.396 35.456,23.887 35.455,22.532 36.355,21.632 SW5.1@36.355,20.391 ; 36.227,37.482 40.294,37.482 v1(40.579,37.767)
NetSB30_1: SB30.1 SK_BT1.1 SW5.3 | length 32.7
  L3 w0.5: v1(37.076,25.758) 37.076,27.16 38.528,28.612 40.928,28.612 41.371,29.055 v1(41.371,40.033)
  L4 w0.3: 30.837,37.928 30.837,38.168 31.481,38.812 34.481,38.812 35.703,40.034 41.351,40.034 v1(41.371,40.033)
  L4 w0.5: SW5.3@36.355,24.891 36.355,25.037 v1(37.076,25.758) ; v1@41.371,40.034 SK_BT1.1@43.93,40.034
NetU1_31: U1.31 U12.A3 | length 1.5
  L1 w0.12: U12.A3@22.844,49.637 U12.A3@22.845,49.638
  L1 w0.265: U1.31@22.844,48.155 U12.A3@22.844,49.637
NetU1_34: U1.34 X1.3 | length 2.1
  L1 w0.2: X1.3@20.202,49.295 20.865,49.295 21.644,48.517 U1.34@21.644,48.155
NetU1_35: U1.35 X1.1 | length 2.8
  L1 w0.2: X1.1@18.632,48.628 19.472,47.789 20.18,47.789 20.517,47.452 U1.35@20.941,47.452
NRST: CN6.3 CN7.14 D1.K JP5.3 SW4.1 | length 101.5
  L1 w0.15: JP5.3@24.247,22.567 24.174,22.494 22.478,22.494 21.608,21.624 21.608,7.516 23.236,5.888 29.002,5.888 29.362,6.248 35.663,6.248 36.486,5.425 36.486,3.422 37.243,2.665 SW4.1@38.386,2.665
  L1 w0.3: CN7.14@5.79,35.52 7.494,37.224 7.494,47.261 v1@8.405,48.171 ; SW4.1@38.386,2.665 SW4.1@42.486,2.665
  L2 w0.3: v1(9.103,21.033) 20.047,21.033 21.581,22.567 JP5.3@24.247,22.567
  L3 w0.3: CN7.14@5.79,35.52 4.555,34.285 4.555,22.316 5.352,21.519 8.268,21.519 8.754,21.033 v1(9.103,21.033)
  L4 w0.3: CN7.14@5.79,35.52 CN6.3@10.87,35.52 ; v1(8.494,48.238) 12.965,48.239 14.206,46.998 D1.K@14.595,46.998
PA0: CN7.34 CN8.4 U1.15 | length 66.3
  L1 w0.2: U1.15@28.722,46.652 32.509,46.652 33.08,46.081 33.08,37.449 32.638,37.007 32.638,36.272 33.053,35.856 33.053,33.991 34.995,32.049 34.995,27.181 32.987,25.173 32.987,23.29 33.195,23.082 33.195,22.514 33.177,22.496 33.177,22.207 33.195,22.189 v1(33.195,21.584)
  L2 w0.2: v1(14.933,19.277) 20.535,19.277 22.385,21.127 28.502,21.127 28.962,21.587 v1@33.19,21.587
  L3 w0.2: CN8.4@10.87,10.12 13.963,13.213 13.963,18.296 v1@14.939,19.271
  L4 w0.3: CN7.34@5.79,10.12 CN8.4@10.87,10.12
PA1: CN8.3 SB14.2 U1.16 | length 61.8
  L1 w0.2: U1.16@28.722,47.052 32.647,47.052 33.38,46.319 33.38,34.156 35.361,32.175 35.361,27.069 33.287,24.995 33.287,23.414 33.527,23.174 v1(33.527,22.351)
  L2 w0.2: v1(14.933,20.091) 20.252,20.091 21.628,21.467 28.094,21.467 28.995,22.368 29.012,22.351 v1(33.527,22.351)
  L3 w0.2: CN8.3@10.87,12.66 13.238,15.028 13.238,18.372 v1@14.945,20.079
  L4 w0.2: CN8.3@10.87,12.66 12.149,13.939 12.803,13.939
PA2: CN9.2 SB15.2 U1.17 | length 73.1
  L1 w0.2: U1.17@28.722,47.452 32.836,47.452 33.76,46.528 33.76,34.291 35.727,32.324 35.727,26.845 33.587,24.705 33.587,23.609 v1(33.637,23.559)
  L2 w0.2: v1(33.637,23.559) 34.035,23.162 34.281,23.162 34.306,23.136 43.553,23.136 43.597,23.18 43.845,23.18 44.336,22.689 47.741,22.689 48.211,23.159 53.325,23.159 53.431,23.053 v1(55.688,23.053)
  L3 w0.2: v1(55.688,23.053) 55.688,22.305 57.201,20.792 57.201,9.509 CN9.2@59.13,7.58
  L4 w0.2: 56.637,8.832 57.194,8.832 57.507,8.519 57.507,7.922 57.849,7.58 CN9.2@59.13,7.58
PA3: CN9.1 CN10.37 U1.18 | length 79.1
  L1 w0.2: U1.18@28.044,48.155 28.044,48.617 v1(28.262,48.835) ; v1(35.083,39.98) 35.083,36.24 35.462,35.861 35.462,34.398 36.974,32.886 36.974,29.588 37.346,29.216 v1(37.638,29.216)
  L2 w0.2: v1(37.638,29.216) 47.665,29.216 49.99,26.891 56.814,26.891 v1(57.061,26.644)
  L3 w0.2: v1(28.262,48.835) 28.262,48.591 29.206,47.647 35.234,47.647 35.514,47.367 35.514,40.406 v1@35.086,39.977 ; v1(57.061,26.644) 57.059,26.642 57.059,26.104 58.65,24.513 60.199,24.513 61.299,23.413 61.299,7.209 CN9.1@59.13,5.04
  L4 w0.2: CN9.1@59.13,5.04 CN10.37@64.21,5.04
PA4: SB5.2 SB41.1 U1.19 | length 39.7
  L1 w0.15: U1.19@27.644,48.404 27.644,48.892 v1(27.689,48.937)
  L2 w0.2: v1(35.164,40.551) 35.635,40.551 35.968,40.218 35.968,39.577 36.666,38.879 v1(55.405,38.879)
  L3 w0.2: v1(27.689,48.937) 27.689,48.621 28.963,47.347 34.959,47.347 35.164,47.142 v1(35.164,40.551)
  L4 w0.1: SB5.2@54.55,37.742 54.688,37.604 ; 55.794,37.604 SB41.1@55.94,37.604
  L4 w0.2: 54.688,37.604 55.794,37.604 55.405,37.993 v1(55.405,38.879)
PA5: CN5.6 CN10.11 U1.20 | length 44.3
  L2 w0.2: v1@34.813,42.12 41.042,42.12 42.791,40.371 57.226,40.371 58.013,39.584 CN5.6@59.13,39.584
  L3 w0.2: v1(27.239,48.728) 27.239,48.519 28.711,47.047 34.428,47.047 34.604,46.871 34.813,46.871 v1(34.813,42.126)
  L4 w0.2: CN5.6@59.13,39.584 60.783,39.584 62.307,38.06 CN10.11@64.21,38.06
PA6: CN5.5 CN10.13 U1.21 | length 50.9
  L1 w0.15: v1(26.806,49.088) 26.844,49.05 U1.21@26.844,48.155
  L2 w0.2: v1(32.73,39.888) 33.124,39.888 34.623,38.389 57.185,38.389 58.53,37.044 CN5.5@59.13,37.044
  L3 w0.2: v1(26.806,49.088) 26.806,47.291 27.35,46.747 33.398,46.747 34.305,45.84 34.305,41.71 33.514,40.919 33.21,40.919 32.73,40.438 v1(32.73,39.888)
  L4 w0.2: CN5.5@59.13,37.044 60.791,37.044 62.315,35.52 CN10.13@64.21,35.52
PA7: CN5.4 SB1.2 U1.22 | length 46.8
  L2 w0.2: v1(32.263,39.736) 32.26,39.733 32.26,38.753 33.373,37.64 37.246,37.64 40.098,34.788 43.043,34.788 v1(43.697,34.134) v1@43.697,34.115
  L3 w0.2: v1(26.441,48.739) 26.441,46.863 26.857,46.447 33.104,46.447 33.81,45.741 33.81,42.065 33.328,41.583 32.775,41.583 32.26,41.068 32.26,39.739 v1(32.263,39.736)
  L4 w0.2: v1(43.697,34.134) 43.699,34.136 49.124,34.136 50.247,35.259 56.158,35.259 ; 56.667,35.417 56.814,35.27 57.291,35.27 58.057,34.504 CN5.4@59.13,34.504
PA8: CN9.7 CN10.25 U1.23 | length 62.9
  L1 w0.15: U1.23@26.05,48.161 v1@26.05,48.985
  L1 w0.2: v1(34.288,46.692) 35.445,46.692 35.829,46.308 35.829,34.69 37.363,33.156 37.363,30.413 38.853,28.923 v1(38.853,26.644)
  L2 w0.2: v1@26.05,48.985 26.05,47.292 26.457,46.885 34.095,46.885 v1(34.288,46.692) ; v1(38.853,26.644) 39.762,26.644 41.444,24.962 56.392,24.962 v1@56.563,24.791
  L3 w0.2: v1(56.563,24.792) 56.562,24.791 56.562,22.848 CN9.7@59.13,20.28
  L4 w0.2: CN9.7@59.13,20.28 CN10.25@64.337,20.28
  other v1: 26.037,48.995
PA9: CN5.2 SB8.2 SB10.1 U1.24 | length 63.3
  L4 w0.2: 24.906,35.859 24.906,36.383 24.024,37.265 24.024,39.868 23.554,40.338 23.554,43.851 25.643,45.94 v1@25.643,48.739 ; 25.224,35.761 25.917,35.761 26.227,35.451 26.227,33.409 26.415,33.221 26.415,32.202 26.103,31.89 24.839,31.89 24.072,31.123 23.115,31.123 22.564,30.572 22.564,28.356 23.321,27.599 23.715,27.599 23.979,27.863 24.269,27.863 24.527,27.605 27.598,27.605 27.853,27.35 29.852,27.35 30.596,28.094 48.995,28.094 49.856,28.955 54.566,28.955 54.995,29.384 55.87,29.384 ; SB8.2@56.09,29.412 59.118,29.412 CN5.2@59.13,29.424
  other v1: 25.642,48.746
PA10: CN9.4 SB3.2 SB11.2 U1.51 | length 87.6
  L1 w0.2: v1@20.937,40.547 20.941,40.551 U1.51@20.941,41.052 ; CN9.4@58.982,12.512 CN9.4@59.13,12.66 60.507,14.037 v1@60.507,30.724 ; v1(60.484,30.726) v1@60.505,30.726
  L3 w0.2: v1@20.937,40.547 21.088,40.396 21.151,40.396 21.501,40.046 22.669,40.046 22.675,40.052 28.714,40.052 v1(29.324,39.442)
  L4 w0.2: v1(29.324,39.442) 29.324,38.928 28.985,38.589 28.985,37.467 28.645,37.127 27.486,37.127 26.737,36.378 26.737,32.1 26.227,31.59 25.172,31.59 24.405,30.823 23.239,30.823 22.997,30.581 22.997,28.718 23.336,28.379 24.48,28.379 24.954,27.905 28.393,27.905 28.642,27.656 29.537,27.656 30.358,28.477 30.401,28.477 45.39,28.477 46.291,29.378 46.291,31.01 47.135,31.854 56.2,31.854 56.2,31.874 ; SB3.2@56.4,31.808 56.4,31.204 56.88,30.724 60.482,30.724 v1(60.484,30.726) ; SB11.2@56.571,13.177 57.232,13.177 57.749,12.66 CN9.4@59.13,12.66
  other v1: 20.945,40.549
PA13: CN7.13 JP5.5 U1.54 | length 59.1
  L1 w0.1: U1.54@22.444,40.349 22.444,39.43 22.449,39.436 v1(22.449,39.463)
  L1 w0.2: CN7.13@3.25,35.52 4.565,34.205 6.582,34.205 7.547,33.24 v1(7.547,24.285)
  L2 w0.2: v1(6.993,39.799) 7.318,39.474 18.716,39.474 18.784,39.542 22.341,39.542 22.428,39.455 22.436,39.463 v1(22.449,39.463) ; v1(7.547,24.285) 7.547,21.168 7.52,21.141 8.448,20.213 11.696,20.213 13.342,18.567 21.018,18.567 22.478,20.027 JP5.5@24.247,20.027
  L4 w0.2: CN7.13@3.25,35.52 4.428,36.698 4.428,38.81 4.996,39.378 6.267,39.378 6.688,39.799 v1(6.993,39.799)
PA14: CN7.15 JP5.7 U1.56 | length 62
  L1 w0.1: CN7.15@3.25,32.98 CN7.15@3.257,32.98 ; v1(23.244,39.444) U1.56@23.244,40.349
  L1 w0.2: CN7.15@3.25,32.98 4.69,31.54 4.69,19.07 v1(4.699,19.061)
  L2 w0.2: v1(4.699,19.061) 7.315,19.061 7.817,19.563 11.622,19.563 13.698,17.487 JP5.7@24.247,17.487 ; v1(6.955,39.208) 7.003,39.16 18.771,39.16 19.501,38.43 22.788,38.43 23.244,38.886 v1(23.244,39.444)
  L4 w0.2: CN7.15@3.25,32.98 4.628,34.358 4.628,36.264 5.159,36.795 6.527,36.795 6.955,37.223 v1(6.955,39.208)
PA15: CN9.6 CN10.27 U1.57 | length 65.7
  L1 w0.2: v1(21.954,27.669) 21.954,31.16 21.01,32.104 21.01,36.148 21.771,36.909 22.063,36.909 23.644,38.49 U1.57@23.644,40.349
  L2 w0.2: v1(21.954,27.669) 22.537,27.086 39.843,27.086 41.605,25.324 55.874,25.324 55.882,25.316 56.172,25.316 56.18,25.324 v1(56.528,25.323)
  L3 w0.2: v1(56.528,25.323) 57.167,24.684 57.167,22.911 58.573,21.505 59.956,21.505 60.539,20.922 60.539,19.149 CN9.6@59.13,17.74
  L4 w0.2: CN9.6@59.13,17.74 CN10.27@64.337,17.74
PB0: CN10.22 R3.1 SB22.1 U1.38 | length 134.3
  L1 w0.15: v1(17.9,40.697) 17.9,40.318 17.526,39.944 17.526,33.843 18.549,32.82 18.549,28.803 19.678,27.673 v1(19.678,26.319) ; v4@18.464,26.303 18.464,25.966 18.192,25.694 18.192,7.631 20.846,4.977 29.54,4.977 29.796,5.233 32.675,5.233 v1(32.669,5.239) ; v1(20.257,46.319) 20.324,46.252 U1.38@20.941,46.252
  L2 w0.15: v1@19.678,26.313 38.998,26.313
  L2 w0.2: v4@18.464,26.294 39.536,26.294 41.254,24.576 56.284,24.576 56.418,24.442 57.62,24.442 57.879,24.701 61.228,24.701 61.669,24.26 65.777,24.26 CN10.22@66.877,25.36
  L3 w0.15: v1(17.9,40.697) 17.9,41.02 17.648,41.272 17.648,45.182 18.281,45.815 19.428,45.815 19.43,45.814 19.752,45.814 v1(20.257,46.319)
  L4 w0.15: SB22.1@15.319,48.724 15.434,48.61 15.752,48.61 16.582,47.78 19.281,47.78 20.257,46.804 v1(20.257,46.319) v1@20.204,46.319 ; v1(32.669,5.239) 33.199,5.239 R3.1@33.205,5.233
  other v4: 18.46,26.303
PB1: CN10.24 R4.1 SB23.1 U1.39 | length 123.8
  L1 w0.15: v1(17.475,40.456) 17.441,40.49 17.202,40.251 17.202,33.617 18.272,32.547 18.272,28.696 18.68,28.287 18.68,26.88 18.891,26.669 18.891,25.919 18.672,25.7 v1(18.672,23.859) 19.339,23.859 19.811,23.387 19.811,7.728 20.307,7.232 20.617,7.232 22.546,5.304 29.367,5.304 29.786,5.723 33.999,5.723 34.489,5.233 v1(34.782,5.233)
  L1 w0.2: v1(19.526,46.408) 20.082,45.852 U1.39@20.941,45.852
  L2 w0.15: v1(13.539,52.457) 13.539,51.806 14.286,51.059 14.286,47.815 14.66,47.441 17.584,47.441 18.292,46.733 18.914,46.733 18.919,46.738 19.196,46.738 v1(19.526,46.408)
  L2 w0.2: v1(18.672,23.859) 18.793,23.98 28.395,23.98 28.541,24.126 28.831,24.126 28.977,23.98 33.082,23.98 33.978,24.875 34.423,24.875 34.454,24.845 34.899,24.845 35.296,24.447 40.958,24.447 41.205,24.201 45.648,24.201 46.033,23.816 58.13,23.816 58.274,23.96 65.737,23.96 CN10.24@66.877,22.82
  L3 w0.15: v1(17.475,40.456) 17.475,40.492 17.36,40.607 17.36,45.427 17.998,46.065 19.183,46.065 v1(19.526,46.408)
  L4 w0.15: 13.007,54.94 13.007,54.847 13.523,54.331 13.523,52.483 v1@13.549,52.457 ; v1(34.782,5.233) R4.1@35.275,5.233
PB2: CN7.2 U1.27 | length 28.2
  L1 w0.15: U1.27@24.428,48.171 U1.27@24.444,48.155 24.444,48.611 24.52,48.686 24.52,49.069 v1(24.543,49.092)
  L4 w0.15: CN7.2@5.79,50.76 7.26,52.229 7.26,55.297 8.122,56.16 11.584,56.16 11.782,55.962 13.156,55.962 13.322,55.796 13.322,54.96 13.841,54.44 13.841,52.924 14.645,52.12 15.105,52.12 15.414,51.811 16.204,51.811 18.089,49.926 18.158,49.926 18.358,49.726 21.642,49.726 21.718,49.802 23.064,49.802 23.494,49.372 24.017,49.372 24.157,49.232 24.372,49.232 24.512,49.092 v1@24.523,49.092 ; v1@24.486,49.055 v1@24.523,49.092 ; v1(24.543,49.092) v1@24.523,49.092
